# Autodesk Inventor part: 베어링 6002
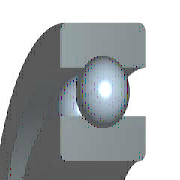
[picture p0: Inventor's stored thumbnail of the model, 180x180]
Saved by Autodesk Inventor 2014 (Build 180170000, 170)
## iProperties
IsCustomPart: 0
Created: 2012-02
Part Number: 베어링 6002
Material: 강철, 연강
Description: 깊은 그루브 볼 베어링
Document SubType Name: Modeling
Standard: KS B 2023
Designer: mduedu
Standards Organization: KS
Language: ko-KR
Size Designation: 6002 - 15 x 32 x 9
Categories: <MemberInstance><Categories><Category DisplayName="샤프트 부품" InternalName="7f7aeb1f-a693-4053-b835-cee3144e0d98" Mnemonic="SHFT"><Category DisplayName="베어링" Inter
Density: 1 g/cm^3
Appearance: 노란색
Author: mduedu
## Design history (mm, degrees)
sketch "스케치" dims "d0" = 4.42 (= -0.26 x WD + 0.26 x BD)
  geometry: L1 (2.29, 11.75)-(6.71, 11.75); L2 (4.5, 11.75)-(4.5, 9.54); L3 (4.5, 11.75)-(4.5, 13.96); L4 (2.858, 10.271)-(0, 10.271); L5 (0, 7.5)-(9, 7.5); L6 (2.858, 13.229)-(0, 13.229); L7 (0, 16)-(9, 16); L8 (9, 7.5)-(9, 10.271); L9 (6.142, 10.271)-(9, 10.271); L10 (6.142, 13.229)-(9, 13.229); L11 (9, 16)-(9, 13.229); L12 (-1.4, 0)-(8.4, 0) reference; L13 (0, -0.3)-(0, 5.3) reference
  constraints: 22 end point, 4 point on line, 2 collinear, 2 perpendicular, 2 symmetric about line, 1 midpoint, 1 parallel, 14 other
  dimensions: "d9" = 15 diameter of L5 L12 (= WD); "d11" = 32 diameter of L7 L12 (= BD); "d12" = 9 distance between parallel lines of L8 L13 (= KB); "d13" = 20.542 diameter of L9 L12 (= 0.326 x BD + 0.674 x WD)
revolve "본체" stored, may be unused: angle "d6" = 90 deg
revolve "볼" stored, may be unused: angle "d7" = 90 deg
pattern_circular "IDS_ARRAYBALL[SIMPL:T]" dims angle "d3" = 360 deg
body "Solid1"
fillet "모깎기1" dims "d1" = 0.3 (= KRS)
other parameters: "WD" = 15 [user parameter; used in 5 equation terms], "BD" = 32 [user parameter; used in 5 equation terms], "KB" = 9 [user parameter; used in 1 equation term], "KRS" = 0.3 [user parameter; used in 1 equation term], "d4" = 0, "d5" = 0, "d8" = 0, "d14" = 0, "d15" = 0, "BBA" = 0 [user parameter], "BC0" = 2850000 [user parameter], "BC" = 5590000 [user parameter], "BR" = 16 (= 0.5 x BD) [user parameter], "WR" = 7.5 (= 0.5 x WD) [user parameter]
